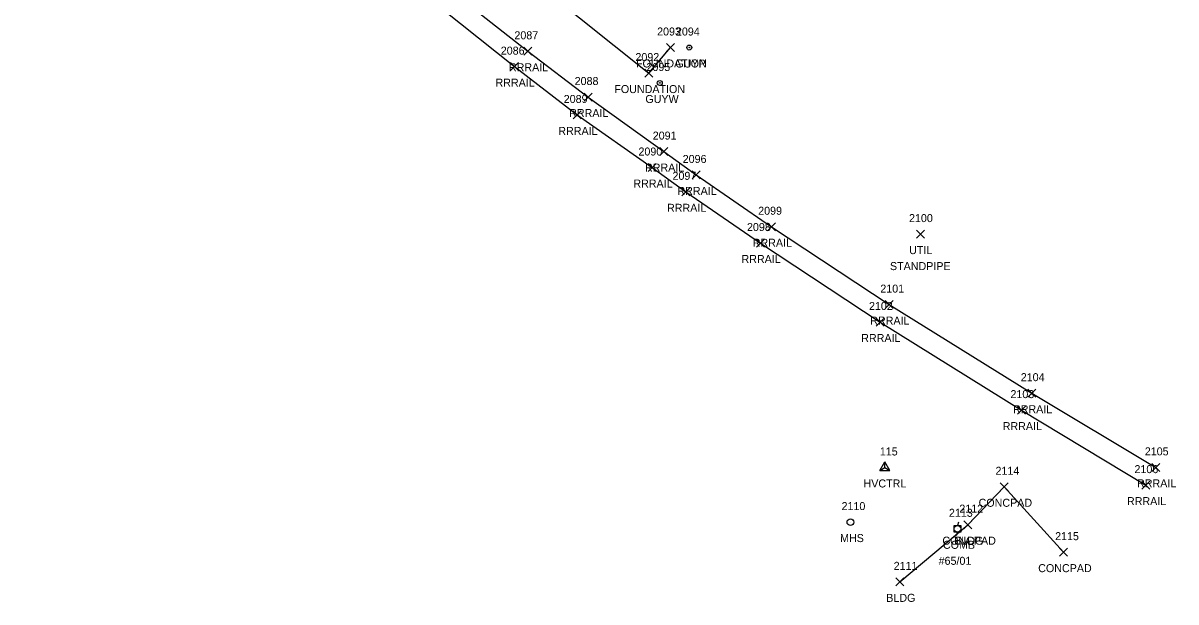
# Model space of a CAD drawing. Extents: x 1635588 to 1637550, y 621583 to 623638.
# Drawn here: x 1637037.4 to 1637325.6, y 621665.4 to 621810.1 of the extents above; entities that cross this region are included whole.
import ezdxf

# ---------------------------------------------------------------- set-up
doc = ezdxf.new("R2010")
doc.units = 0
for name, color, linetype in [('C_A', 7, 'Continuous'), ('C_I', 7, 'Continuous'), ('CPSM', 7, 'Continuous'), ('L_A', 7, 'Continuous'), ('L_I', 7, 'Continuous'), ('L_TIC', 7, 'Continuous'), ('LBC', 7, 'Continuous'), ('LS', 7, 'Continuous'), ('R_A', 7, 'Continuous'), ('R_I', 7, 'Continuous'), ('R_TIC', 7, 'Continuous'), ('RR', 7, 'Continuous'), ('U_A', 7, 'Continuous'), ('U_C', 7, 'Continuous'), ('U_I', 7, 'Continuous'), ('UDEFAULT', 7, 'Continuous'), ('UP', 7, 'Continuous'), ('UPGW', 7, 'Continuous'), ('USMH', 7, 'Continuous')]:
    doc.layers.add(name, color=color, linetype=linetype)

msp = doc.modelspace()

# ---------------------------------------------------------------- linework, layer by layer
at = {"layer": 'CPSM'}
for p, q in [((1637251.56, 621698.28), (1637252.81, 621700.45)), ((1637251.56, 621698.28), (1637252.81, 621699.01)), ((1637251.56, 621698.28), (1637254.06, 621698.28)), ((1637254.06, 621698.28), (1637252.81, 621700.45)), ((1637252.81, 621699.01), (1637252.81, 621700.45)), ((1637252.81, 621699.01), (1637252.81, 621699.01)), ((1637252.81, 621699.01), (1637254.06, 621698.28))]:
    msp.add_line(p, q, dxfattribs=at)
at = {"layer": 'L_TIC'}
for points in [[(1637198.24, 621803.01), (1637200.24, 621805.01)], [(1637200.24, 621803.01), (1637198.24, 621805.01)], [(1637192.82, 621796.61), (1637194.82, 621798.61)], [(1637194.82, 621796.61), (1637192.82, 621798.61)], [(1637281.63, 621693.18), (1637283.63, 621695.18)], [(1637283.63, 621693.18), (1637281.63, 621695.18)], [(1637272.57, 621683.7), (1637274.57, 621685.7)], [(1637274.57, 621683.7), (1637272.57, 621685.7)], [(1637272.57, 621683.7), (1637274.57, 621685.7)], [(1637274.57, 621683.7), (1637272.57, 621685.7)], [(1637296.52, 621676.83), (1637298.52, 621678.83)], [(1637298.52, 621676.83), (1637296.52, 621678.83)], [(1637255.6, 621669.41), (1637257.6, 621671.41)], [(1637257.6, 621669.41), (1637255.6, 621671.41)]]:
    msp.add_lwpolyline(points, dxfattribs=at)
at = {"layer": 'LBC'}
for points in [[(1637127.75, 621845.35), (1637128.26, 621844.95), (1637131.72, 621847.95), (1637150.11, 621832.58), (1637193.82, 621797.61), (1637199.24, 621804.01)], [(1637256.6, 621670.41), (1637273.57, 621684.7)]]:
    msp.add_lwpolyline(points, dxfattribs=at)
at = {"layer": 'LS'}
msp.add_lwpolyline([(1637273.57, 621684.7), (1637282.63, 621694.18), (1637297.52, 621677.83)], dxfattribs=at)
at = {"layer": 'R_TIC'}
for points in [[(1637162.57, 621802.06), (1637164.57, 621804.06)], [(1637164.57, 621802.06), (1637162.57, 621804.06)], [(1637159.21, 621798.22), (1637161.21, 621800.22)], [(1637161.21, 621798.22), (1637159.21, 621800.22)], [(1637177.63, 621790.62), (1637179.63, 621792.62)], [(1637179.63, 621790.62), (1637177.63, 621792.62)], [(1637174.91, 621786.14), (1637176.91, 621788.14)], [(1637176.91, 621786.14), (1637174.91, 621788.14)], [(1637196.58, 621776.98), (1637198.58, 621778.98)], [(1637198.58, 621776.98), (1637196.58, 621778.98)], [(1637193.67, 621773), (1637195.67, 621775)], [(1637195.67, 621773), (1637193.67, 621775)], [(1637204.69, 621771.14), (1637206.69, 621773.14)], [(1637206.69, 621771.14), (1637204.69, 621773.14)], [(1637202.09, 621766.92), (1637204.09, 621768.92)], [(1637204.09, 621766.92), (1637202.09, 621768.92)], [(1637223.52, 621758.19), (1637225.52, 621760.19)], [(1637225.52, 621758.19), (1637223.52, 621760.19)], [(1637220.71, 621754.12), (1637222.71, 621756.12)], [(1637222.71, 621754.12), (1637220.71, 621756.12)], [(1637252.9, 621738.72), (1637254.9, 621740.72)], [(1637254.9, 621738.72), (1637252.9, 621740.72)], [(1637250.64, 621734.37), (1637252.64, 621736.37)], [(1637252.64, 621734.37), (1637250.64, 621736.37)], [(1637288.58, 621716.58), (1637290.58, 621718.58)], [(1637290.58, 621716.58), (1637288.58, 621718.58)], [(1637286.01, 621712.34), (1637288.01, 621714.34)], [(1637288.01, 621712.34), (1637286.01, 621714.34)], [(1637319.59, 621698.03), (1637321.59, 621700.03)], [(1637321.59, 621698.03), (1637319.59, 621700.03)], [(1637317.07, 621693.59), (1637319.07, 621695.59)], [(1637319.07, 621693.59), (1637317.07, 621695.59)]]:
    msp.add_lwpolyline(points, dxfattribs=at)
at = {"layer": 'RR'}
for points in [[(1637026.25, 621930.62), (1637051.37, 621903.17), (1637074.4, 621880.01), (1637083.38, 621871.59), (1637115.01, 621842.98), (1637140.82, 621820.97), (1637163.57, 621803.06), (1637178.63, 621791.62), (1637197.58, 621777.98), (1637205.69, 621772.14), (1637224.52, 621759.19), (1637253.9, 621739.72), (1637289.58, 621717.58), (1637320.59, 621699.03)], [(1637027.08, 621922.66), (1637047.82, 621899.75), (1637071.19, 621876.23), (1637080.21, 621867.76), (1637112.17, 621839), (1637137.72, 621817.24), (1637160.21, 621799.22), (1637175.91, 621787.14), (1637194.67, 621774), (1637203.09, 621767.92), (1637221.71, 621755.12), (1637251.64, 621735.37), (1637287.01, 621713.34), (1637318.07, 621694.59)]]:
    msp.add_lwpolyline(points, dxfattribs=at)
at = {"layer": 'UDEFAULT'}
for points in [[(1637260.73, 621756.35), (1637262.73, 621758.35)], [(1637262.73, 621756.35), (1637260.73, 621758.35)]]:
    msp.add_lwpolyline(points, dxfattribs=at)
at = {"layer": 'UP'}
for p, q in [((1637270.14, 621682.84), (1637270.14, 621684.5)), ((1637270.14, 621684.5), (1637271.81, 621684.5)), ((1637271.22, 621685.34), (1637270.97, 621684.5)), ((1637270.97, 621683.67), (1637270.97, 621683.67)), ((1637271.81, 621684.5), (1637271.81, 621682.84)), ((1637271.81, 621682.84), (1637270.14, 621682.84)), ((1637270.72, 621682), (1637270.97, 621682.84))]:
    msp.add_line(p, q, dxfattribs=at)
msp.add_circle((1637270.97, 621683.67), 0.833, dxfattribs=at)
at = {"layer": 'UPGW'}
for centre, radius in [((1637203.95, 621804), 0.625), ((1637203.95, 621804), 0.0833), ((1637196.58, 621795.13), 0.625), ((1637196.58, 621795.13), 0.0833)]:
    msp.add_circle(centre, radius, dxfattribs=at)
at = {"layer": 'USMH'}
for p, q in [((1637244.22, 621685.35), (1637244.22, 621685.35)), ((1637245.06, 621685.35), (1637245.06, 621685.35))]:
    msp.add_line(p, q, dxfattribs=at)
msp.add_circle((1637244.22, 621685.35), 0.833, dxfattribs=at)

# ---------------------------------------------------------------- texts
at = {"layer": 'C_A'}
msp.add_text('HVCTRL', height=2, dxfattribs=at).set_placement((1637247.5, 621694.01))
at = {"layer": 'C_I'}
msp.add_text('115', height=2, dxfattribs=at).set_placement((1637251.58, 621702.01))
at = {"layer": 'L_A'}
for s, p in [('FOUNDATION', (1637190.63, 621799.01)), ('FOUNDATION', (1637185.21, 621792.61)), ('CONCPAD', (1637276.27, 621689.18)), ('CONCPAD', (1637267.22, 621679.7)), ('BLDG', (1637270.16, 621679.7)), ('CONCPAD', (1637291.17, 621672.83)), ('BLDG', (1637253.19, 621665.41))]:
    msp.add_text(s, height=2, dxfattribs=at).set_placement(p)
at = {"layer": 'L_I'}
for s, p in [('2093', (1637195.9, 621807.01)), ('2092', (1637190.48, 621800.61)), ('2114', (1637280.5, 621697.18)), ('2112', (1637271.45, 621687.7)), ('2112', (1637271.45, 621687.7)), ('2115', (1637295.4, 621680.83)), ('2111', (1637255.04, 621673.41))]:
    msp.add_text(s, height=2, dxfattribs=at).set_placement(p)
at = {"layer": 'R_A'}
for p in [(1637158.86, 621798.06), (1637155.5, 621794.22), (1637173.92, 621786.62), (1637171.2, 621782.14), (1637192.87, 621772.98), (1637189.96, 621769), (1637200.98, 621767.14), (1637198.38, 621762.92), (1637219.81, 621754.19), (1637217, 621750.12), (1637249.19, 621734.72), (1637246.93, 621730.37), (1637284.87, 621712.58), (1637282.3, 621708.34), (1637315.88, 621694.03), (1637313.36, 621689.59)]:
    msp.add_text('RRRAIL', height=2, dxfattribs=at).set_placement(p)
at = {"layer": 'R_I'}
for s, p in [('2087', (1637160.23, 621806.06)), ('2086', (1637156.82, 621802.22)), ('2088', (1637175.29, 621794.62)), ('2089', (1637172.56, 621790.14)), ('2091', (1637194.81, 621780.98)), ('2090', (1637191.24, 621777)), ('2096', (1637202.3, 621775.14)), ('2097', (1637199.75, 621770.92)), ('2099', (1637221.17, 621762.19)), ('2098', (1637218.37, 621758.12)), ('2101', (1637251.7, 621742.72)), ('2102', (1637248.87, 621738.37)), ('2104', (1637286.81, 621720.58)), ('2103', (1637284.23, 621716.34)), ('2105', (1637317.82, 621702.03)), ('2106', (1637315.24, 621697.59))]:
    msp.add_text(s, height=2, dxfattribs=at).set_placement(p)
at = {"layer": 'U_A'}
for s, p in [('GUYP', (1637200.46, 621799)), ('GUYW', (1637192.97, 621790.13)), ('UTIL', (1637258.9, 621752.35)), ('MHS', (1637241.64, 621680.35)), ('COMB', (1637267.36, 621678.67))]:
    msp.add_text(s, height=2, dxfattribs=at).set_placement(p)
at = {"layer": 'U_C'}
for s, p in [('STANDPIPE', (1637254.11, 621748.35)), ('#65/01', (1637266.28, 621674.67))]:
    msp.add_text(s, height=2, dxfattribs=at).set_placement(p)
at = {"layer": 'U_I'}
for s, p in [('2094', (1637200.61, 621807)), ('2095', (1637193.24, 621798.13)), ('2100', (1637258.88, 621760.35)), ('2110', (1637242.01, 621688.35)), ('2113', (1637268.85, 621686.67))]:
    msp.add_text(s, height=2, dxfattribs=at).set_placement(p)

doc.saveas('drawing.dxf')
